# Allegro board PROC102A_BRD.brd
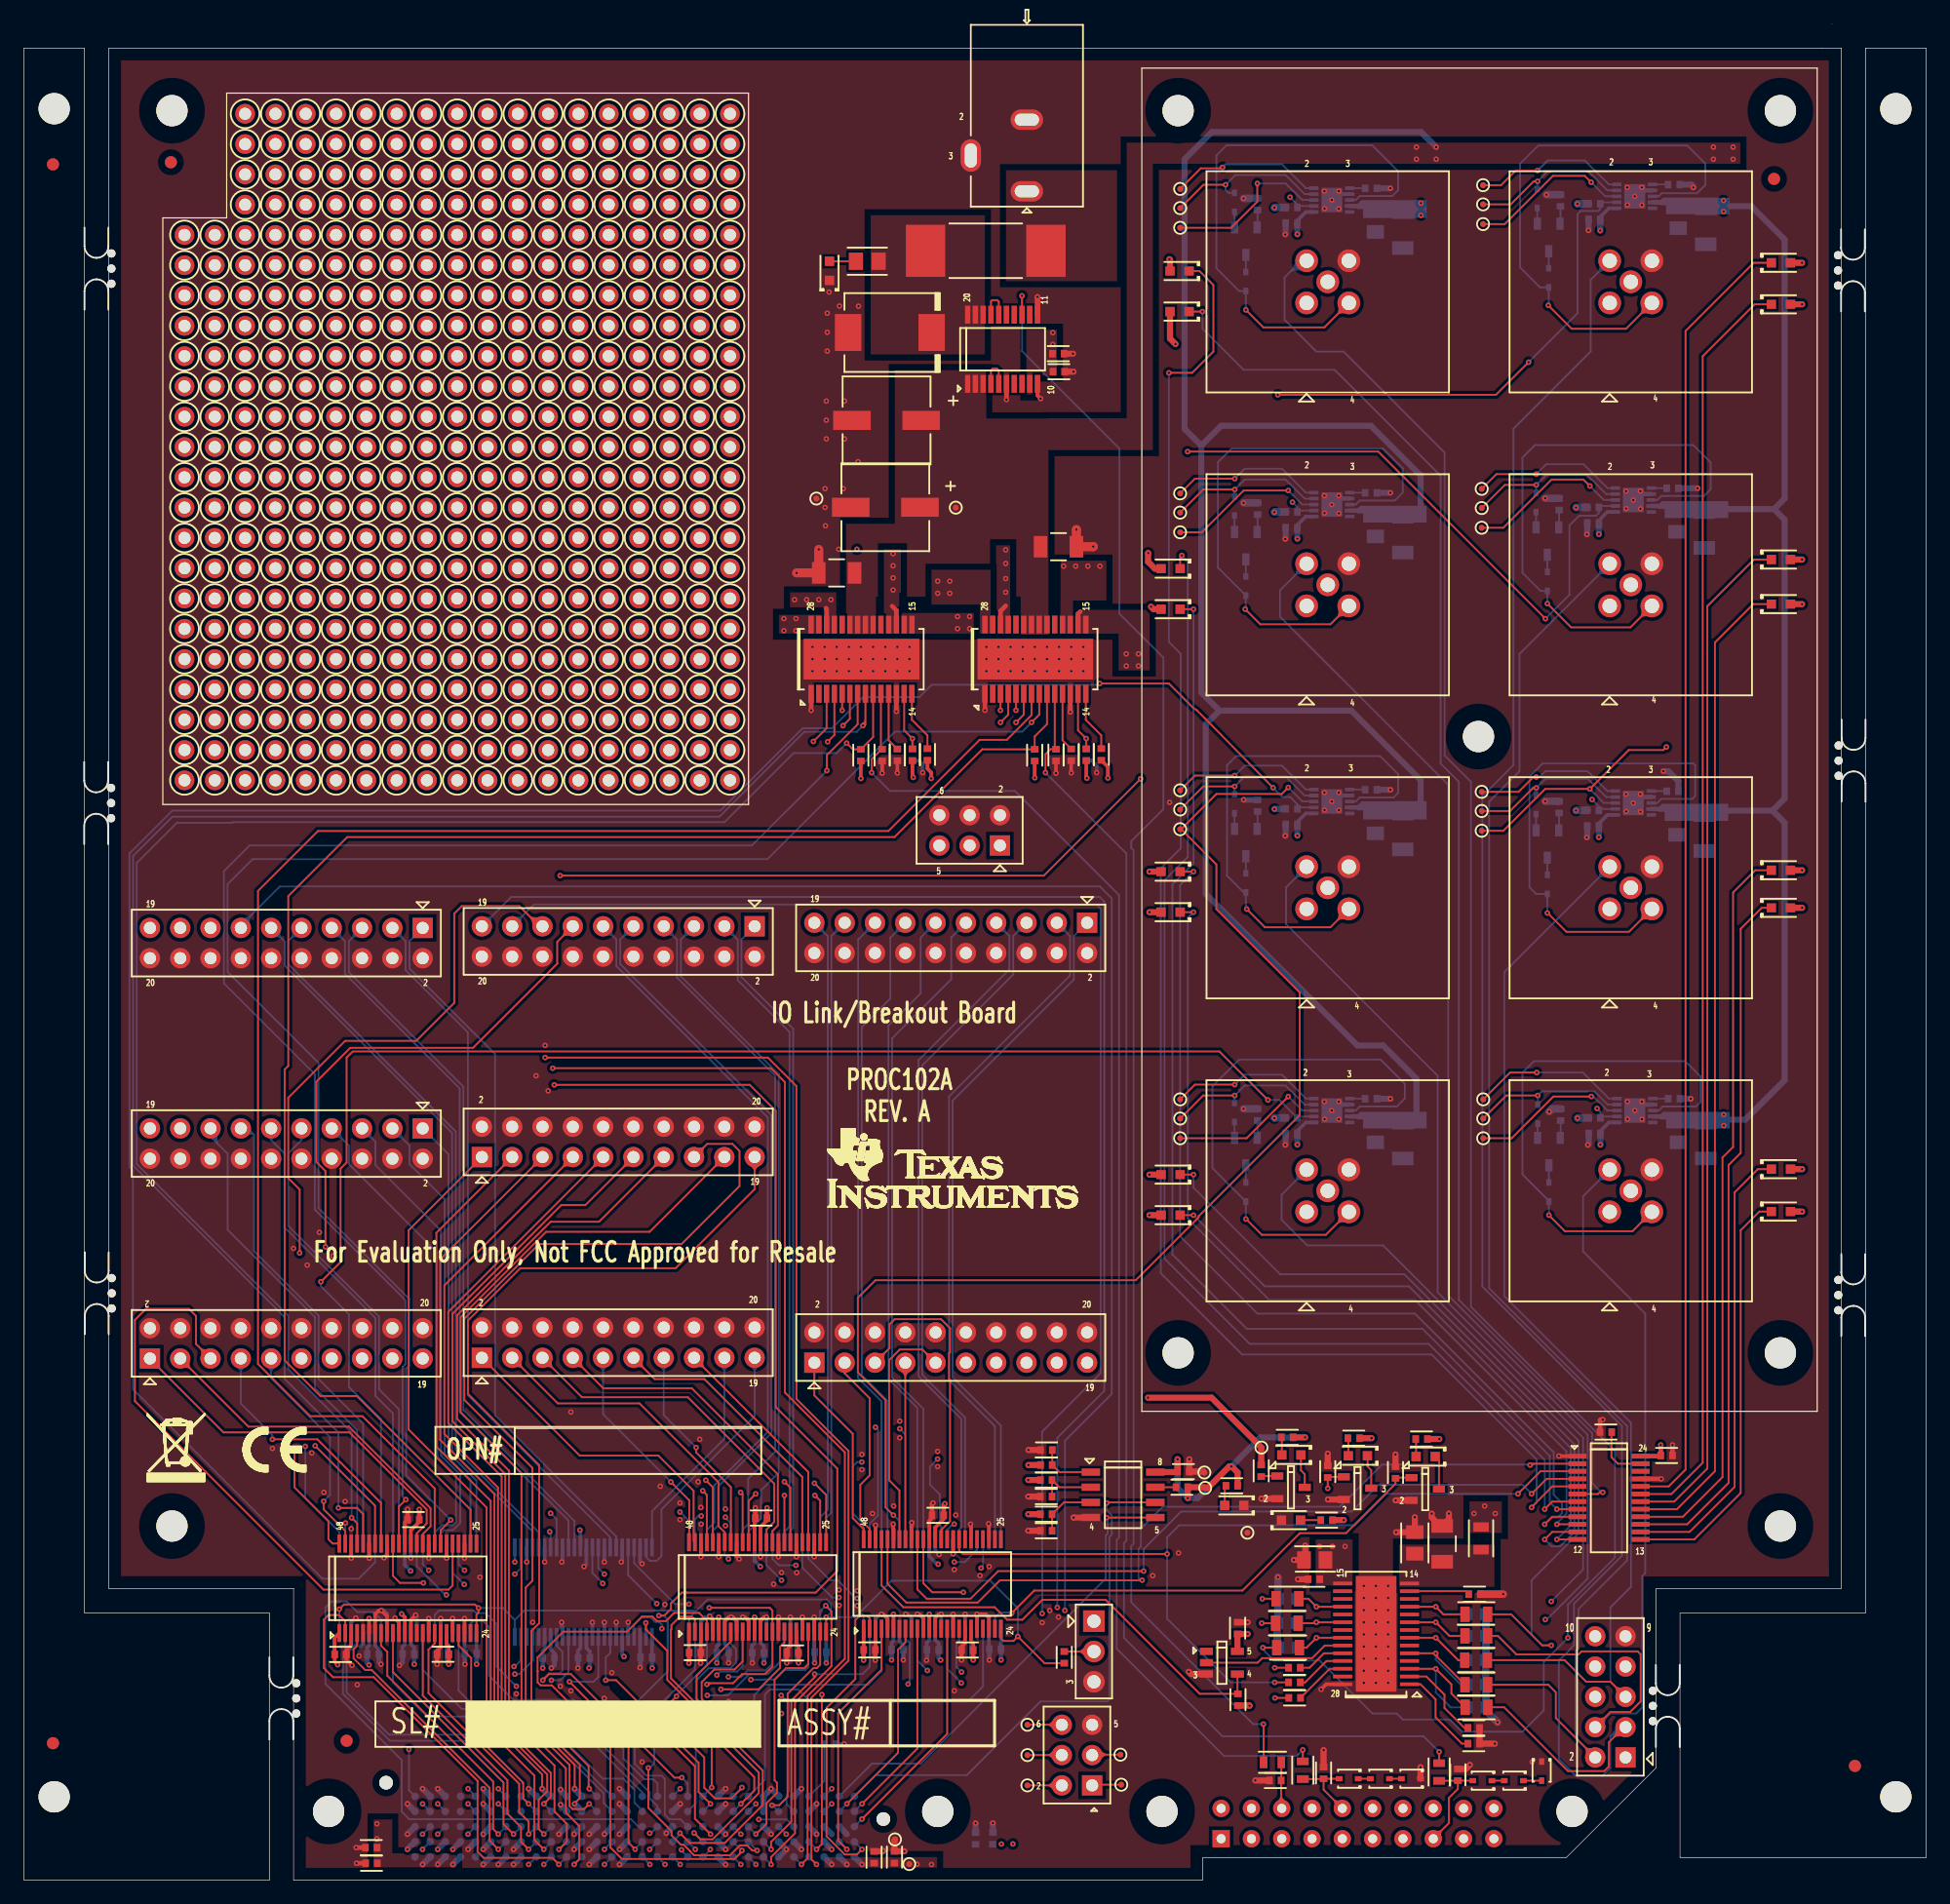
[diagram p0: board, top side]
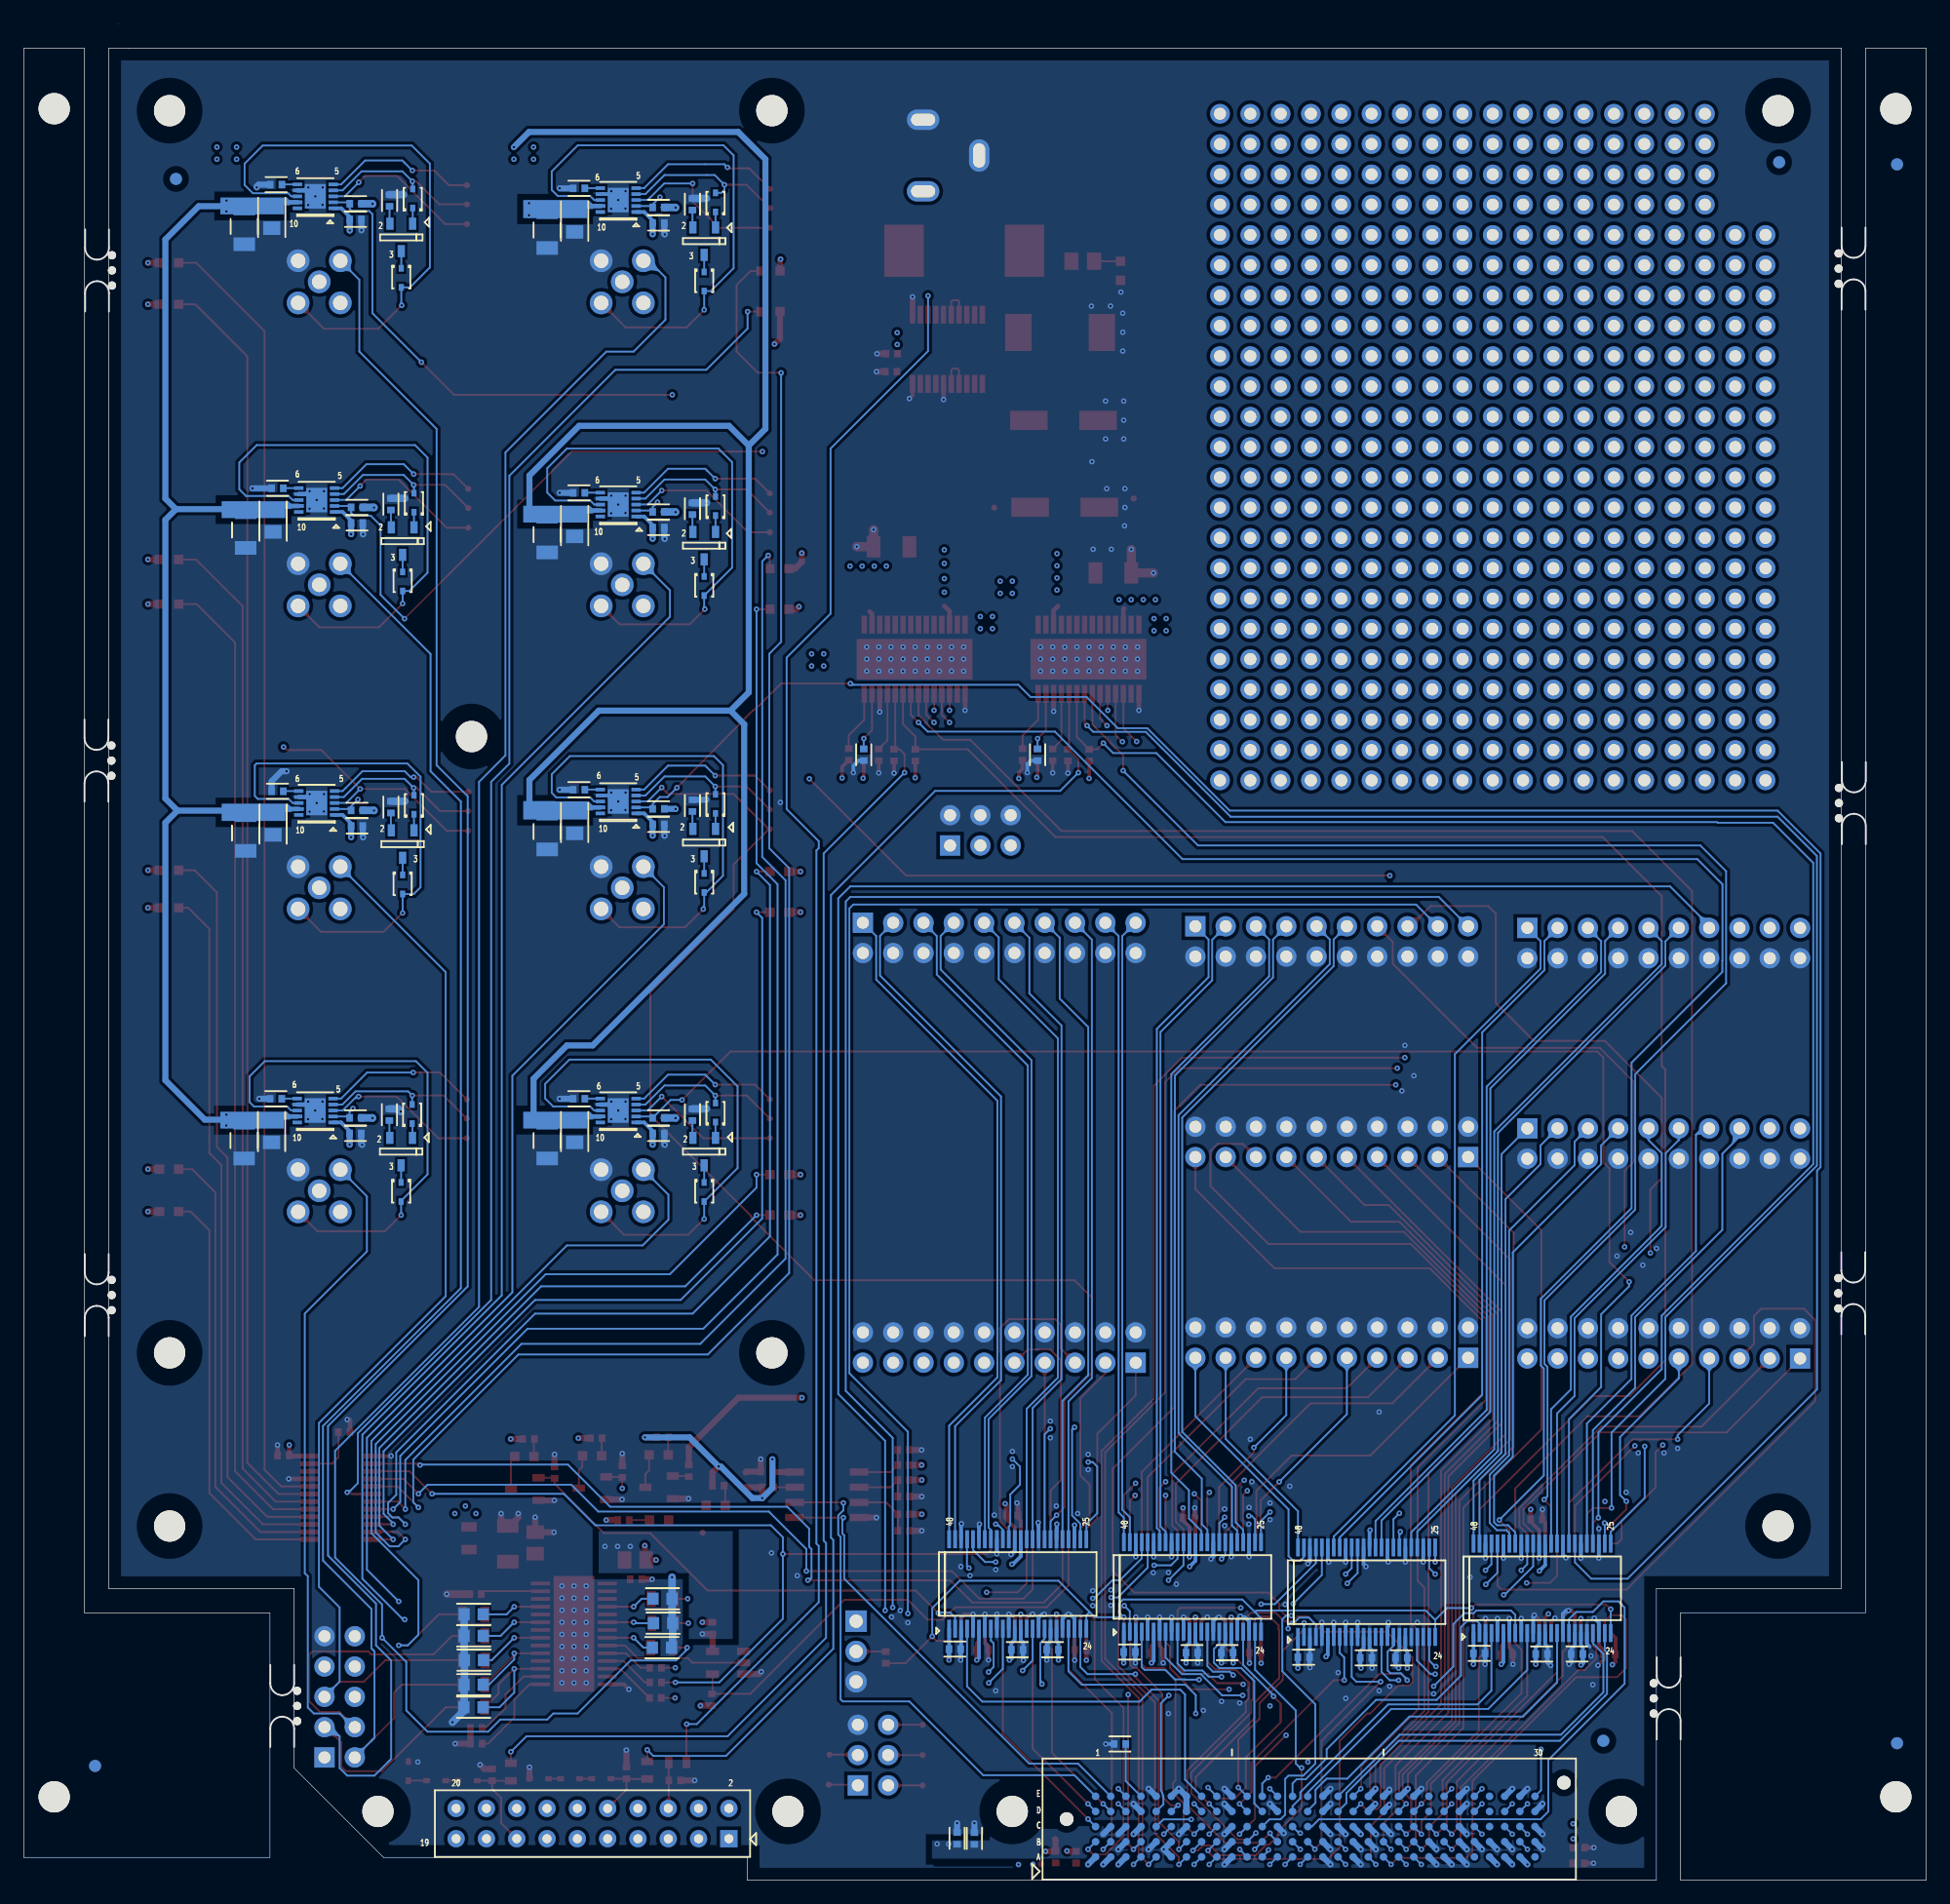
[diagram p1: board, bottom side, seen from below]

Outline 159.44 x 155.62 mm; copper layers: TOP, L02_GND1, L03_SIG1, L04_PWR, L05_GND2, BOTTOM. Coordinates in mm from the lower left corner of the outline.
Outline path: 0,153.59 5.08,153.59 5.08,22.42 20.58,22.42 20.58,0 0,0 0,153.59 ; 7.11,153.59 150.7,153.59 150.7,153.59 152.31,153.59 152.32,153.58 152.32,24.44 136.78,24.44 136.78,9.4 129.29,1.91 98.81,1.91 98.81,0 22.61,0 22.61,24.45 7.11,24.45 7.11,153.59 ; 138.81,22.41 154.35,22.41 154.35,153.59 159.44,153.59 159.44,1.91 138.81,1.91 138.81,22.41

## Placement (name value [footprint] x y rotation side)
C1  0.1uF  [CAP0402_0-75]  97.18 34.25 180 top
C2  1uF  [CAP0402_0-75]  81.22 3.51 90 bottom
C3  0.1uF  [CAP0402_0-75]  79.77 3.49 90 bottom
C4  1uF  [CAP0402_0-75]  29.14 1.42 180 top
C5  0.1uF  [CAP0402_0-75]  29.11 2.73 180 top
C6  1uF  [CAP0402_0-75]  72.97 1.93 90 top
C7  0.1uF  [CAP0402_0-75]  71.26 1.92 90 top
C8  0.1uF  [CAP0402_0-75]  81.41 19.37 180 bottom
C9  0.1uF  [CAP0402_0-75]  76.18 19.32 180 bottom
C10  0.1uF  [CAP0402_0-75]  73.22 19.32 0 bottom
C15  0.1uF  [CAP0402_0-75]  58.57 19.07 0 bottom
C16  0.1uF  [CAP0402_0-75]  66.76 19.12 180 bottom
C17  0.1uF  [CAP0402_0-75]  61.54 19.07 180 bottom
C20  0.1uF  [CAP0402_0-75]  61.79 30.36 180 top
C21  0.1uF  [CAP0402_0-75]  56.25 19.07 0 top
C22  0.1uF  [CAP0402_0-75]  64.43 19.05 180 top
C25  0.1uF  [CAP0402_0-75]  52.17 18.69 180 bottom
C26  0.1uF  [CAP0402_0-75]  43.98 18.64 0 bottom
C27  0.1uF  [CAP0402_0-75]  46.94 18.64 180 bottom
C30  0.1uF  [CAP0402_0-75]  32.23 18.96 180 bottom
C31  0.1uF  [CAP0402_0-75]  29.27 18.96 0 bottom
C32  0.1uF  [CAP0402_0-75]  37.46 19.01 180 bottom
C33  0.1uF  [CAP0402_0-75]  26.54 18.92 0 top
C34  0.1uF  [CAP0402_0-75]  35.13 18.94 180 top
C35  0.1uF  [CAP0402_0-75]  32.65 30.22 180 top
C44  0.1uF  [CAP0402_0-75]  70.88 19.3 0 top
C45  0.1uF  [CAP0402_0-75]  79.08 19.3 180 top
C46  0.1uF  [CAP0402_0-75]  76.6 30.58 180 top
C63  0.1uF  [CAP0402_0-75]  137.68 35.6 0 top
C64  1uF  [CAP0402_0-75]  131.52 113.78 180 bottom
C65  1uF  [CAP0402_0-75]  131.63 139.24 180 bottom
C66  10uF  [CAP1206_2]  140.96 138.64 270 bottom
C67  1uF  [CAP0805_1-5]  138.66 139.39 270 bottom
C68  10uF  [CAP1206_2]  140.85 113.19 270 bottom
C69  1uF  [CAP0805_1-5]  138.55 113.93 270 bottom
C70  10uF  [CAP1206_2]  140.97 62 270 bottom
C71  1uF  [CAP0805_1-5]  138.67 62.75 270 bottom
C72  1uF  [CAP0402_0-75]  131.65 62.6 180 bottom
C73  1uF  [CAP0402_0-75]  131.52 88.38 180 bottom
C74  1uF  [CAP0805_1-5]  138.55 88.53 270 bottom
C75  10uF  [CAP1206_2]  140.85 87.79 270 bottom
C76  10uF  [CAP1206_2]  115.57 87.91 270 bottom
C77  1uF  [CAP0805_1-5]  113.27 88.66 270 bottom
C78  1uF  [CAP0402_0-75]  106.25 88.5 180 bottom
C79  10uF  [CAP1206_2]  115.57 62 270 bottom
C80  1uF  [CAP0805_1-5]  113.27 62.75 270 bottom
C81  1uF  [CAP0402_0-75]  106.25 62.6 180 bottom
C82  1uF  [CAP0402_0-75]  106.25 138.92 180 bottom
C83  10uF  [CAP1206_2]  115.57 138.33 270 bottom
C84  1uF  [CAP0805_1-5]  113.27 139.08 270 bottom
C85  1uF  [CAP0402_0-75]  106.25 113.4 180 bottom
C86  10uF  [CAP1206_2]  115.57 112.8 270 bottom
C87  1uF  [CAP0805_1-5]  113.27 113.55 270 bottom
C88  10uF  [CAP1206_2]  86.72 111.79 0 top
C89  10uF  [CAP1206_2]  68.12 109.59 180 top
C90  0.001uF  [CAP0805_1]  116.58 28.27 90 top
C91  10uF  [CAP1206_2]  118.87 28.2 90 top
C92  2.2uF  [CAP0805_1-5]  108.19 26.84 180 top
C93  0.01uF  [CAP0402_0-75]  108.13 25.23 180 top
C94  0.01uF  [CAP0402_0-75]  101.73 21.13 90 top
C95  0.022uF  [CAP0603_1]  121.75 14.49 0 bottom
C96  0.022uF  [CAP0603_1]  121.74 16.38 0 bottom
C97  0.022uF  [CAP0603_1]  121.71 18.44 0 bottom
C98  0.022uF  [CAP0603_1]  121.74 20.48 0 bottom
C99  0.022uF  [CAP0603_1]  121.74 22.29 0 bottom
C100  0.022uF  [CAP0603_1]  105.91 23.59 180 bottom
C101  0.022uF  [CAP0603_1]  105.86 21.54 180 bottom
C102  0.022uF  [CAP0603_1]  105.96 19.49 180 bottom
C103  1uF  [CAP0402_0-75]  104.89 8.36 180 top
C104  0.1uF  [CAP0402_0-75]  108.93 8.99 90 top
C105  0.1uF  [CAP0402_0-75]  120.18 8.83 90 top
C106  1uF  [CAP0402_0-75]  86.7 127.97 0 top
C107  0.1uF  [CAP0402_0-75]  86.75 126.46 0 top
C108  100uF_35V  [CAPAE_DCASE_6-1]  72.3 122.38 180 top
C109  100uF_35V  [CAPAE_DCASE_6-1]  72.2 115.1 180 top
D1  1N4148WT  [DIO_SOD523]  127.8 134.33 270 bottom
D2  1N4148WT  [DIO_SOD523]  127.69 108.87 270 bottom
D3  1N4148WT  [DIO_SOD523]  127.82 57.69 270 bottom
D4  1N4148WT  [DIO_SOD523]  127.69 83.47 270 bottom
D5  1N4148WT  [DIO_SOD523]  102.42 83.6 270 bottom
D6  1N4148WT  [DIO_SOD523]  102.42 57.69 270 bottom
D7  1N4148WT  [DIO_SOD523]  102.42 134.02 270 bottom
D8  1N4148WT  [DIO_SOD523]  102.42 108.49 270 bottom
D9  1N4148WT  [DIO_SOD523]  111.04 8.5 180 top
D10  1N4148WT  [DIO_SOD523]  122.24 8.34 180 top
D11  1N4148WT  [DIO_SOD523]  113.65 8.5 180 top
D12  1N4148WT  [DIO_SOD523]  124.88 8.34 180 top
D13  1N4148WT  [DIO_SOD523]  116.26 8.5 180 top
D14  1N4148WT  [DIO_SOD523]  127.21 9.14 270 top
D15  SMCJ28A  [DIO_SMC]  72.58 129.74 180 top
D16  1N4148WT  [DIO_SOD523]  126.84 140.98 90 bottom
D17  1N4148WT  [DIO_SOD523]  126.74 115.48 90 bottom
D18  1N4148WT  [DIO_SOD523]  126.74 90.16 90 bottom
D19  1N4148WT  [DIO_SOD523]  126.89 64.22 90 bottom
D20  1N4148WT  [DIO_SOD523]  101.47 64.35 90 bottom
D21  1N4148WT  [DIO_SOD523]  101.47 90.23 90 bottom
D22  1N4148WT  [DIO_SOD523]  101.47 115.2 90 bottom
D23  1N4148WT  [DIO_SOD523]  101.47 140.65 90 bottom
DN1  CON_T4141012051-000_CIRDIN5  [CON_CIRDIN5_T4141012051_S_S_T_23]  132.91 132.23 90 top
DN2  CON_T4141012051-000_CIRDIN5  [CON_CIRDIN5_T4141012051_S_S_T_23]  132.91 106.83 90 top
DN3  CON_T4141012051-000_CIRDIN5  [CON_CIRDIN5_T4141012051_S_S_T_23]  132.91 81.43 90 top
DN4  CON_T4141012051-000_CIRDIN5  [CON_CIRDIN5_T4141012051_S_S_T_23]  132.91 56.03 90 top
DN5  CON_T4141012051-000_CIRDIN5  [CON_CIRDIN5_T4141012051_S_S_T_23]  107.51 56.03 90 top
DN6  CON_T4141012051-000_CIRDIN5  [CON_CIRDIN5_T4141012051_S_S_T_23]  107.51 81.43 90 top
DN7  CON_T4141012051-000_CIRDIN5  [CON_CIRDIN5_T4141012051_S_S_T_23]  107.51 106.83 90 top
DN8  CON_T4141012051-000_CIRDIN5  [CON_CIRDIN5_T4141012051_S_S_T_23]  107.51 132.23 90 top
F1  10A  [FUSE_397_410X110_SMD_2-9]  80.62 136.6 180 top
J1  CON_XMC_5X30_M  [CON_XMC5X30_SEAM-30-03-5-05-2-A_P_S_S_7-5]  51.2 5.12 180 bottom
J2  HDR_2X10  [HDR_2X10_TSW_100_S_T]  89.11 80.26 0 top
J3  HDR_2X10  [HDR_2X10_TSW_100_S_T]  61.25 79.97 0 top
J4  HDR_2X10  [HDR_2X10_TSW_100_S_T]  38.39 43.79 180 top
J5  HDR_2X10  [HDR_2X10_TSW_100_S_T]  33.43 79.83 0 top
J6  HDR_2X10  [HDR_2X10_TSW_100_S_T]  33.43 63.02 0 top
J7  HDR_2X10  [HDR_2X10_TSW_100_S_T]  38.39 60.62 180 top
J8  HDR_2X10  [HDR_2X10_TSW_100_S_T]  10.57 43.73 180 top
J9  HDR_2X10  [HDR_2X10_TSW_100_S_T]  66.25 43.38 180 top
J11  HDR_1X3  [HDR_3X1_100_S_T]  89.68 21.71 90 top
J12  RECP_2X10  [RECPT_2X10_68683-310_S_T_7-1]  100.35 3.47 0 bottom
J13  CON_PWRJACK3_PJ-102AH  [CON_PWRJACK3_PJ-102AH_P_R_T_11]  84.07 141.58 180 top
J17  RECP_2X3  [RECPT_2X3_PPTC032LFBN_S_T_8-5]  81.81 86.74 180 top
J18  HDR_2X3  [HDR_2X3_TSW-103-07-D_S_T_8-4]  89.53 7.95 90 top
J21  HDR_2X5  [HDR_5X2_100_S_T_8-6]  134.24 10.29 270 top
LD1  150060VS75000  [LED_150060SS75000_70X40_SMD_0-8]  117.49 35.51 180 top
LD2  150060VS75000  [LED_150060SS75000_70X40_SMD_0-8]  111.81 35.58 180 top
LD3  150060VS75000  [LED_150060SS75000_70X40_SMD_0-8]  106.2 30.18 0 top
LD4  150060VS75000  [LED_150060SS75000_70X40_SMD_0-8]  101.45 31.42 180 top
LD5  150060VS75000  [LED_150060SS75000_70X40_SMD_0-8]  106.23 35.65 180 top
LD6  150060RS55040  [LED_150060RS55040_70X40_SMD_0-5]  96.86 134.9 180 top
LD7  150060VS75000  [LED_150060SS75000_70X40_SMD_0-8]  96.86 131.5 180 top
LD8  150060RS55040  [LED_150060RS55040_70X40_SMD_0-5]  96.11 109.95 180 top
LD9  150060VS75000  [LED_150060SS75000_70X40_SMD_0-8]  96.11 106.55 180 top
LD10  150060RS55040  [LED_150060RS55040_70X40_SMD_0-5]  96.11 84.55 180 top
LD11  150060VS75000  [LED_150060SS75000_70X40_SMD_0-8]  96.11 81.15 180 top
LD12  150060RS55040  [LED_150060RS55040_70X40_SMD_0-5]  96.11 59.15 180 top
LD13  150060VS75000  [LED_150060SS75000_70X40_SMD_0-8]  96.11 55.75 180 top
LD14  150060RS55040  [LED_150060RS55040_70X40_SMD_0-5]  147.26 56.05 0 top
LD15  150060VS75000  [LED_150060SS75000_70X40_SMD_0-8]  147.26 59.6 0 top
LD16  150060RS55040  [LED_150060RS55040_70X40_SMD_0-5]  147.26 81.51 0 top
LD17  150060VS75000  [LED_150060SS75000_70X40_SMD_0-8]  147.26 84.66 0 top
LD18  150060RS55040  [LED_150060RS55040_70X40_SMD_0-5]  147.26 106.98 0 top
LD19  150060VS75000  [LED_150060SS75000_70X40_SMD_0-8]  147.26 110.71 0 top
LD20  150060RS55040  [LED_150060RS55040_70X40_SMD_0-5]  147.26 132.11 0 top
LD21  150060VS75000  [LED_150060SS75000_70X40_SMD_0-8]  147.26 135.59 0 top
LD22  150060VS75000  [LED_150060SS75000_70X40_SMD_0-8]  67.52 134.92 90 top
NOREF  -  []  29.47 14.99 0 top
NOREF#2  -  [unnamed#2]  95.39 5.76 0 top
NOREF#3  -  [unnamed#3]  36.32 112.52 0 top
NOREF#4  -  []  12.41 29.69 90 top
NOREF#5  -  [unnamed#3]  26.16 112.52 0 top
NOREF#6  -  [unnamed#3]  46.48 104.9 0 top
NOREF#7  -  [unnamed#3]  59.18 125.22 0 top
NOREF#8  -  [unnamed#3]  28.7 120.14 0 top
NOREF#9  -  [unnamed#3]  49.02 117.6 0 top
NOREF#10  -  [unnamed#3]  41.4 143 0 top
NOREF#11  -  [unnamed#3]  51.56 112.52 0 top
NOREF#12  -  [unnamed#3]  56.64 117.6 0 top
NOREF#13  -  [unnamed#3]  59.18 115.06 0 top
NOREF#14  -  [unnamed#3]  18.54 127.76 0 top
NOREF#15  -  [unnamed#3]  38.86 127.76 0 top
NOREF#16  -  [unnamed#3]  51.56 125.22 0 top
NOREF#17  -  [unnamed#3]  38.86 122.68 0 top
NOREF#18  -  [unnamed#3]  41.4 102.36 0 top
NOREF#19  -  [unnamed#3]  56.64 109.98 0 top
NOREF#20  -  [unnamed#3]  16 97.28 0 top
NOREF#21  -  [unnamed#3]  31.24 125.22 0 top
NOREF#22  -  [unnamed#3]  23.62 92.2 0 top
NOREF#23  -  [unnamed#3]  46.48 143 0 top
NOREF#24  -  [unnamed#3]  26.16 140.46 0 top
NOREF#25  -  [unnamed#3]  16 120.14 0 top
NOREF#26  -  [unnamed#3]  26.16 120.14 0 top
NOREF#27  -  [unnamed#3]  31.24 109.98 0 top
NOREF#28  -  [unnamed#4]  6.11 49.2 270 top
NOREF#29  -  [unnamed#3]  13.46 117.6 0 top
NOREF#30  -  [unnamed#3]  21.08 143 0 top
NOREF#31  -  [unnamed#3]  33.78 135.38 0 top
NOREF#32  -  [unnamed#3]  46.48 109.98 0 top
NOREF#33  -  [unnamed#3]  38.86 132.84 0 top
NOREF#34  -  [unnamed#3]  49.02 140.46 0 top
NOREF#35  -  [unnamed#3]  33.78 143 0 top
NOREF#36  -  [unnamed#3]  31.24 94.74 0 top
NOREF#37  -  [unnamed#3]  59.18 137.92 0 top
NOREF#38  -  [unnamed#3]  18.54 125.22 0 top
NOREF#39  -  [unnamed#3]  46.48 94.74 0 top
NOREF#40  -  [unnamed#3]  41.4 140.46 0 top
NOREF#41  -  [unnamed#3]  56.64 140.46 0 top
NOREF#42  -  [unnamed#3]  41.4 94.74 0 top
NOREF#43  -  [unnamed#3]  59.18 140.46 0 top
NOREF#44  -  [unnamed#3]  33.78 92.2 0 top
NOREF#45  -  [unnamed#3]  49.02 135.38 0 top
NOREF#46  -  [unnamed#3]  26.16 117.6 0 top
NOREF#47  -  [unnamed#3]  41.4 148.08 0 top
NOREF#48  -  [unnamed#3]  21.08 102.36 0 top
NOREF#49  -  [unnamed#3]  36.32 135.38 0 top
NOREF#50  -  [unnamed#3]  26.16 145.54 0 top
NOREF#51  -  [unnamed#3]  31.24 97.28 0 top
NOREF#52  -  [unnamed#3]  31.24 107.44 0 top
NOREF#53  -  [unnamed#3]  59.18 104.9 0 top
NOREF#54  -  [unnamed#3]  28.7 92.2 0 top
NOREF#55  -  [unnamed#3]  21.08 107.44 0 top
NOREF#56  -  [unnamed#3]  54.1 112.52 0 top
NOREF#57  -  [unnamed#3]  16 117.6 0 top
NOREF#58  -  [unnamed#4]  137.78 14.61 90 top
NOREF#59  -  []  0 153.59 0 top
NOREF#60  -  [unnamed#3]  49.02 107.44 0 top
NOREF#61  -  [unnamed#3]  36.32 94.74 0 top
NOREF#62  -  [unnamed#3]  59.18 130.3 0 top
NOREF#63  -  [unnamed#3]  41.4 92.2 0 top
NOREF#64  -  [unnamed#3]  31.24 92.2 0 top
NOREF#65  -  [unnamed#3]  38.86 117.6 0 top
NOREF#66  -  [unnamed#3]  23.62 145.54 0 top
NOREF#67  -  [unnamed#3]  26.16 130.3 0 top
NOREF#68  -  [unnamed#3]  46.48 97.28 0 top
NOREF#69  -  [unnamed#3]  13.46 107.44 0 top
NOREF#70  -  [unnamed#2]  156.9 148.51 0 top
NOREF#71  -  [unnamed#3]  54.1 140.46 0 top
NOREF#72  -  [unnamed#3]  51.56 140.46 0 top
NOREF#73  -  [unnamed#3]  43.94 112.52 0 top
NOREF#74  -  [unnamed#3]  41.4 107.44 0 top
NOREF#75  -  [unnamed#3]  49.02 130.3 0 top
NOREF#76  -  [unnamed#3]  36.32 148.08 0 top
NOREF#77  -  [unnamed#3]  23.62 135.38 0 top
NOREF#78  -  [unnamed#3]  51.56 130.3 0 top
NOREF#79  -  [unnamed#3]  18.54 140.46 0 top
NOREF#80  -  [unnamed#3]  33.78 107.44 0 top
NOREF#81  -  []  0 0 90 top
NOREF#82  -  [unnamed#3]  31.24 137.92 0 top
NOREF#83  -  [unnamed#3]  33.78 137.92 0 top
NOREF#84  -  [unnamed#3]  18.54 135.38 0 top
NOREF#85  -  [unnamed#3]  43.94 143 0 top
NOREF#86  -  [unnamed#3]  38.86 97.28 0 top
NOREF#87  -  [unnamed#3]  26.16 143 0 top
NOREF#88  -  [unnamed#3]  33.78 140.46 0 top
NOREF#89  -  [unnamed#3]  21.08 145.54 0 top
NOREF#90  -  [unnamed#3]  46.48 140.46 0 top
NOREF#91  -  [unnamed#3]  36.32 92.2 0 top
NOREF#92  -  [unnamed#3]  13.46 125.22 0 top
NOREF#93  -  [unnamed#2]  25.54 5.76 0 top
NOREF#94  -  [unnamed#3]  56.64 130.3 0 top
NOREF#95  -  [unnamed#3]  31.24 135.38 0 top
NOREF#96  -  [unnamed#3]  36.32 107.44 0 top
NOREF#97  -  [unnamed#3]  36.32 125.22 0 top
NOREF#98  -  [unnamed#2]  147.22 44.2 0 top
NOREF#99  -  [unnamed#2]  2.44 11.48 0 top
NOREF#100  -  [unnamed#3]  28.7 115.06 0 top
NOREF#101  -  [unnamed#3]  23.62 130.3 0 top
NOREF#102  -  [unnamed#2]  12.41 29.69 0 top
NOREF#103  -  [unnamed#2]  2.44 143.84 0 top
NOREF#104  -  [unnamed#3]  33.78 109.98 0 top
NOREF#105  -  [unnamed#3]  43.94 132.84 0 top
NOREF#106  -  [unnamed#3]  38.86 140.46 0 top
NOREF#107  -  [unnamed#3]  56.64 104.9 0 top
NOREF#108  -  [unnamed#3]  38.86 99.82 0 top
NOREF#109  -  [unnamed#3]  54.1 132.84 0 top
NOREF#110  -  [unnamed#3]  28.7 102.36 0 top
NOREF#111  -  [unnamed#3]  33.78 122.68 0 top
NOREF#112  -  [unnamed#3]  59.18 120.14 0 top
NOREF#113  -  [unnamed#3]  46.48 107.44 0 top
NOREF#114  -  [unnamed#3]  16 135.38 0 top
NOREF#115  -  [unnamed#3]  38.86 120.14 0 top
NOREF#116  -  [unnamed#3]  31.24 120.14 0 top
NOREF#117  -  [unnamed#3]  54.1 94.74 0 top
NOREF#118  -  [unnamed#3]  41.4 135.38 0 top
NOREF#119  -  [unnamed#3]  59.18 99.82 0 top
NOREF#120  -  [unnamed#3]  28.7 132.84 0 top
NOREF#121  -  [unnamed#3]  13.46 97.28 0 top
NOREF#122  -  [unnamed#3]  49.02 102.36 0 top
NOREF#123  -  [unnamed#3]  54.1 117.6 0 top
NOREF#124  -  [unnamed#3]  33.78 104.9 0 top
NOREF#125  -  [unnamed#3]  26.16 135.38 0 top
NOREF#126  -  [unnamed#3]  26.16 107.44 0 top
NOREF#127  -  [unnamed#3]  28.7 135.38 0 top
NOREF#128  -  [unnamed#3]  38.86 130.3 0 top
NOREF#129  -  [unnamed#3]  26.16 132.84 0 top
NOREF#130  -  [unnamed#3]  36.32 99.82 0 top
NOREF#131  -  [unnamed#3]  41.4 130.3 0 top
NOREF#132  -  [unnamed#3]  41.4 109.98 0 top
NOREF#133  -  [unnamed#3]  51.56 132.84 0 top
NOREF#134  -  [unnamed#3]  56.64 145.54 0 top
NOREF#135  -  [unnamed#3]  41.4 137.92 0 top
NOREF#136  -  [unnamed#3]  51.56 135.38 0 top
NOREF#137  -  [unnamed#3]  31.24 132.84 0 top
NOREF#138  -  [unnamed#3]  43.94 127.76 0 top
NOREF#139  -  [unnamed#3]  23.62 104.9 0 top
NOREF#140  -  [unnamed#3]  43.94 148.08 0 top
NOREF#141  -  [unnamed#3]  46.48 120.14 0 top
NOREF#142  -  [unnamed#3]  46.48 130.3 0 top
NOREF#143  -  [unnamed#3]  33.78 102.36 0 top
NOREF#144  -  [unnamed#3]  16 125.22 0 top
NOREF#145  -  [unnamed#4]  153.3 134.95 90 top
NOREF#146  -  [unnamed#3]  18.54 92.2 0 top
NOREF#147  -  [unnamed#3]  31.24 143 0 top
NOREF#148  -  [unnamed#3]  41.4 117.6 0 top
NOREF#149  -  [unnamed#3]  49.02 143 0 top
NOREF#150  -  [unnamed#3]  41.4 99.82 0 top
NOREF#151  -  [unnamed#4]  6.08 135.1 270 top
NOREF#152  -  [unnamed#3]  16 132.84 0 top
NOREF#153  -  [unnamed#3]  51.56 97.28 0 top
NOREF#154  -  [unnamed#3]  36.32 120.14 0 top
NOREF#155  -  [unnamed#3]  43.94 115.06 0 top
NOREF#156  -  [unnamed#3]  59.18 97.28 0 top
NOREF#157  -  [unnamed#3]  41.4 104.9 0 top
NOREF#158  -  [unnamed#3]  59.18 127.76 0 top
NOREF#159  -  [unnamed#3]  26.16 122.68 0 top
NOREF#160  -  [unnamed#3]  13.46 137.92 0 top
NOREF#161  -  [unnamed#3]  49.02 92.2 0 top
NOREF#162  -  [unnamed#3]  43.94 97.28 0 top
NOREF#163  -  [unnamed#3]  51.56 107.44 0 top
NOREF#164  -  [unnamed#3]  16 112.52 0 top
NOREF#165  -  [unnamed#3]  46.48 112.52 0 top
NOREF#166  -  [unnamed#3]  13.46 127.76 0 top
NOREF#167  -  [unnamed#3]  36.32 130.3 0 top
NOREF#168  -  [unnamed#3]  18.54 130.3 0 top
NOREF#169  -  [unnamed#3]  54.1 135.38 0 top
NOREF#170  -  [unnamed#3]  54.1 115.06 0 top
NOREF#171  -  [unnamed#3]  41.4 145.54 0 top
NOREF#172  -  [unnamed#3]  21.08 109.98 0 top
NOREF#173  -  [unnamed#3]  49.02 97.28 0 top
NOREF#174  -  [unnamed#3]  18.54 137.92 0 top
NOREF#175  -  [unnamed#3]  31.24 115.06 0 top
NOREF#176  -  [unnamed#3]  13.46 132.84 0 top
NOREF#177  -  [unnamed#3]  43.94 135.38 0 top
NOREF#178  -  [unnamed#3]  23.62 125.22 0 top
NOREF#179  -  [unnamed#3]  46.48 145.54 0 top
NOREF#180  -  [unnamed#3]  56.64 137.92 0 top
NOREF#181  -  [unnamed#3]  31.24 104.9 0 top
NOREF#182  -  [unnamed#3]  23.62 143 0 top
NOREF#183  -  [unnamed#3]  21.08 132.84 0 top
NOREF#184  -  [unnamed#3]  36.32 97.28 0 top
NOREF#185  -  [unnamed#3]  49.02 120.14 0 top
NOREF#186  -  [unnamed#3]  38.86 107.44 0 top
NOREF#187  -  [unnamed#3]  23.62 115.06 0 top
NOREF#188  -  [unnamed#3]  56.64 107.44 0 top
NOREF#189  -  [unnamed#3]  26.16 92.2 0 top
NOREF#190  -  [unnamed#4]  21.58 15.24 270 top
NOREF#191  -  [unnamed#3]  43.94 92.2 0 top
NOREF#192  -  [unnamed#3]  26.16 94.74 0 top
NOREF#193  -  [unnamed#3]  28.7 107.44 0 top
NOREF#194  -  [unnamed#3]  33.78 99.82 0 top
NOREF#195  -  [unnamed#3]  38.86 115.06 0 top
NOREF#196  -  [unnamed#3]  23.62 102.36 0 top
NOREF#197  -  [unnamed#3]  59.18 143 0 top
NOREF#198  -  [unnamed#3]  31.24 112.52 0 top
NOREF#199  -  [unnamed#3]  33.78 145.54 0 top
NOREF#200  -  [unnamed#3]  18.54 132.84 0 top
NOREF#201  -  [unnamed#3]  38.86 92.2 0 top
NOREF#202  -  [unnamed#3]  49.02 148.08 0 top
NOREF#203  -  [unnamed#3]  43.94 130.3 0 top
NOREF#204  -  []  27.41 -97.56 0 top
NOREF#205  -  [unnamed#3]  49.02 132.84 0 top
NOREF#206  -  [unnamed#3]  21.08 148.08 0 top
NOREF#207  -  [unnamed#3]  23.62 148.08 0 top
NOREF#208  -  [unnamed#2]  2.54 6.99 0 top
NOREF#209  -  [unnamed#3]  56.64 125.22 0 top
NOREF#210  -  [unnamed#2]  121.92 95.87 0 top
NOREF#211  -  [unnamed#3]  46.48 122.68 0 top
NOREF#212  -  [unnamed#3]  41.4 122.68 0 top
NOREF#213  -  [unnamed#3]  28.7 125.22 0 top
NOREF#214  -  [unnamed#3]  54.1 143 0 top
NOREF#215  -  [unnamed#2]  153.47 9.58 0 top
NOREF#216  -  [unnamed#3]  33.78 115.06 0 top
NOREF#217  -  [unnamed#3]  18.54 109.98 0 top
NOREF#218  -  [unnamed#3]  56.64 120.14 0 top
NOREF#219  -  [unnamed#3]  46.48 137.92 0 top
NOREF#220  -  [unnamed#3]  31.24 117.6 0 top
NOREF#221  -  [unnamed#3]  18.54 102.36 0 top
NOREF#222  -  [unnamed#3]  33.78 130.3 0 top
NOREF#223  -  [unnamed#3]  28.7 94.74 0 top
NOREF#224  -  [unnamed#3]  46.48 115.06 0 top
NOREF#225  -  [unnamed#3]  38.86 137.92 0 top
NOREF#226  -  [unnamed#3]  43.94 102.36 0 top
NOREF#227  -  [unnamed#3]  31.24 99.82 0 top
NOREF#228  -  [unnamed#3]  13.46 112.52 0 top
NOREF#229  -  [unnamed#3]  51.56 127.76 0 top
NOREF#230  -  [unnamed#3]  36.32 143 0 top
NOREF#231  -  [unnamed#3]  18.54 120.14 0 top
NOREF#232  -  []  12.41 148.34 0 top
NOREF#233  -  [unnamed#3]  36.32 132.84 0 top
NOREF#234  -  [unnamed#3]  26.16 115.06 0 top
NOREF#235  -  [unnamed#3]  33.78 127.76 0 top
NOREF#236  -  [unnamed#3]  16 99.82 0 top
NOREF#237  -  [unnamed#3]  26.16 125.22 0 top
NOREF#238  -  [unnamed#3]  18.54 107.44 0 top
NOREF#239  -  [unnamed#3]  16 137.92 0 top
NOREF#240  -  [unnamed#3]  31.24 148.08 0 top
NOREF#241  -  [unnamed#3]  33.78 112.52 0 top
NOREF#242  -  [unnamed#3]  28.7 117.6 0 top
NOREF#243  -  [unnamed#3]  51.56 102.36 0 top
NOREF#244  -  [unnamed#3]  28.7 145.54 0 top
NOREF#245  -  [unnamed#3]  54.1 104.9 0 top
NOREF#246  -  [unnamed#3]  26.16 97.28 0 top
NOREF#247  -  [unnamed#3]  36.32 115.06 0 top
NOREF#248  -  [unnamed#3]  16 92.2 0 top
NOREF#249  -  [unnamed#3]  56.64 135.38 0 top
NOREF#250  -  [unnamed#3]  41.4 97.28 0 top
NOREF#251  -  [unnamed#3]  33.78 125.22 0 top
NOREF#252  -  [unnamed#3]  21.08 120.14 0 top
NOREF#253  -  [unnamed#4]  153.33 49.05 90 top
NOREF#254  -  [unnamed#3]  21.08 117.6 0 top
NOREF#255  -  [unnamed#3]  18.54 115.06 0 top
NOREF#256  -  [unnamed#3]  43.94 109.98 0 top
NOREF#257  -  [unnamed#3]  38.86 102.36 0 top
NOREF#258  -  [unnamed#3]  38.86 125.22 0 top
NOREF#259  -  [unnamed#3]  18.54 117.6 0 top
NOREF#260  -  [unnamed#3]  38.86 143 0 top
NOREF#261  -  [unnamed#3]  51.56 122.68 0 top
NOREF#262  -  [unnamed#3]  23.62 120.14 0 top
NOREF#263  -  [unnamed#3]  21.08 99.82 0 top
NOREF#264  -  [unnamed#3]  28.7 140.46 0 top
NOREF#265  -  [unnamed#3]  51.56 115.06 0 top
NOREF#266  -  [unnamed#3]  18.54 148.08 0 top
NOREF#267  -  [unnamed#3]  49.02 109.98 0 top
NOREF#268  -  [unnamed#3]  13.46 115.06 0 top
NOREF#269  -  [unnamed#3]  31.24 140.46 0 top
NOREF#270  -  [unnamed#3]  18.54 143 0 top
NOREF#271  -  [unnamed#3]  16 102.36 0 top
NOREF#272  -  [unnamed#3]  13.46 92.2 0 top
NOREF#273  -  [unnamed#3]  49.02 99.82 0 top
NOREF#274  -  [unnamed#3]  28.7 112.52 0 top
NOREF#275  -  [unnamed#3]  16 127.76 0 top
NOREF#276  -  [unnamed#3]  59.18 145.54 0 top
NOREF#277  -  [unnamed#3]  56.64 92.2 0 top
NOREF#278  -  [unnamed#3]  31.24 127.76 0 top
NOREF#279  -  []  95.39 5.76 0 top
NOREF#280  -  [unnamed#3]  16 130.3 0 top
NOREF#281  -  [unnamed#3]  56.64 122.68 0 top
NOREF#282  -  [unnamed#4]  6.06 90.3 270 top
NOREF#283  -  [unnamed#3]  23.62 140.46 0 top
NOREF#284  -  [unnamed#3]  51.56 120.14 0 top
NOREF#285  -  [unnamed#3]  43.94 122.68 0 top
NOREF#286  -  [unnamed#3]  21.08 115.06 0 top
NOREF#287  -  [unnamed#3]  59.18 135.38 0 top
NOREF#288  -  [unnamed#3]  54.1 130.3 0 top
NOREF#289  -  [unnamed#3]  18.54 145.54 0 top
NOREF#290  -  [unnamed#2]  12.41 148.34 0 top
NOREF#291  -  [unnamed#3]  36.32 145.54 0 top
NOREF#292  -  [unnamed#3]  16 122.68 0 top
NOREF#293  -  []  -404.06 -63.87 0 top
NOREF#294  -  [unnamed#3]  36.32 104.9 0 top
NOREF#295  -  [unnamed#3]  18.54 94.74 0 top
NOREF#296  -  [unnamed#3]  13.46 135.38 0 top
NOREF#297  -  [unnamed#3]  41.4 125.22 0 top
NOREF#298  -  [unnamed#3]  33.78 148.08 0 top
NOREF#299  -  [unnamed#3]  49.02 112.52 0 top
NOREF#300  -  [unnamed#3]  23.62 117.6 0 top
NOREF#301  -  [unnamed#3]  51.56 109.98 0 top
NOREF#302  -  [unnamed#3]  26.16 109.98 0 top
NOREF#303  -  [unnamed#3]  38.86 148.08 0 top
NOREF#304  -  [unnamed#3]  13.46 94.74 0 top
NOREF#305  -  [unnamed#3]  49.02 145.54 0 top
NOREF#306  -  [unnamed#3]  18.54 99.82 0 top
NOREF#307  -  [unnamed#3]  23.62 94.74 0 top
NOREF#308  -  [unnamed#3]  46.48 132.84 0 top
NOREF#309  -  [unnamed#3]  21.08 97.28 0 top
NOREF#310  -  [unnamed#3]  21.08 112.52 0 top
NOREF#311  -  [unnamed#3]  49.02 127.76 0 top
NOREF#312  -  [unnamed#2]  76.6 5.76 0 top
NOREF#313  -  [unnamed#3]  46.48 148.08 0 top
NOREF#314  -  [unnamed#2]  146.69 142.62 0 top
NOREF#315  -  [unnamed#3]  51.56 117.6 0 top
NOREF#316  -  [unnamed#3]  28.7 137.92 0 top
NOREF#317  -  [unnamed#3]  31.24 130.3 0 top
NOREF#318  -  [unnamed#3]  43.94 120.14 0 top
NOREF#319  -  [unnamed#3]  26.16 127.76 0 top
NOREF#320  -  [unnamed#3]  59.18 109.98 0 top
NOREF#321  -  [unnamed#3]  49.02 137.92 0 top
NOREF#322  -  [unnamed#3]  23.62 99.82 0 top
NOREF#323  -  [unnamed#3]  26.16 148.08 0 top
NOREF#324  -  [unnamed#3]  18.54 112.52 0 top
NOREF#325  -  [unnamed#3]  16 109.98 0 top
NOREF#326  -  [unnamed#3]  56.64 127.76 0 top
NOREF#327  -  [unnamed#3]  28.7 143 0 top
NOREF#328  -  []  -52.42 47.01 0 top
NOREF#329  -  [unnamed#3]  56.64 132.84 0 top
NOREF#330  -  []  25.54 5.76 0 top
NOREF#331  -  [unnamed#3]  23.62 97.28 0 top
NOREF#332  -  [unnamed#3]  21.08 92.2 0 top
NOREF#333  -  [unnamed#3]  36.32 127.76 0 top
NOREF#334  -  [unnamed#3]  59.18 122.68 0 top
NOREF#335  -  [unnamed#3]  21.08 135.38 0 top
NOREF#336  -  [unnamed#3]  33.78 132.84 0 top
NOREF#337  -  [unnamed#3]  59.18 92.2 0 top
NOREF#338  -  [unnamed#3]  54.1 127.76 0 top
NOREF#339  -  [unnamed#3]  23.62 127.76 0 top
NOREF#340  -  [unnamed#3]  26.16 99.82 0 top
NOREF#341  -  [unnamed#3]  13.46 109.98 0 top
NOREF#342  -  [unnamed#3]  56.64 112.52 0 top
NOREF#343  -  [unnamed#2]  129.76 5.76 0 top
NOREF#344  -  [unnamed#2]  96.74 44.2 0 top
NOREF#345  -  [unnamed#3]  46.48 102.36 0 top
NOREF#346  -  [unnamed#3]  21.08 104.9 0 top
NOREF#347  -  [unnamed#2]  2.54 148.51 0 top
NOREF#348  -  [unnamed#3]  59.18 102.36 0 top
NOREF#349  -  [unnamed#3]  21.08 137.92 0 top
NOREF#350  -  [unnamed#3]  13.46 122.68 0 top
NOREF#351  -  [unnamed#3]  28.7 130.3 0 top
NOREF#352  -  [unnamed#3]  46.48 127.76 0 top
NOREF#353  -  [unnamed#3]  51.56 148.08 0 top
NOREF#354  -  [unnamed#3]  13.46 130.3 0 top
NOREF#355  -  [unnamed#3]  51.56 92.2 0 top
NOREF#356  -  [unnamed#3]  31.24 145.54 0 top
NOREF#357  -  [unnamed#3]  43.94 94.74 0 top
NOREF#358  -  [unnamed#3]  56.64 102.36 0 top
NOREF#359  -  [unnamed#3]  31.24 122.68 0 top
NOREF#360  -  [unnamed#3]  28.7 97.28 0 top
NOREF#361  -  [unnamed#3]  28.7 127.76 0 top
NOREF#362  -  [unnamed#3]  59.18 107.44 0 top
NOREF#363  -  [unnamed#3]  46.48 125.22 0 top
NOREF#364  -  [unnamed#3]  21.08 122.68 0 top
NOREF#365  -  [unnamed#3]  51.56 104.9 0 top
NOREF#366  -  [unnamed#3]  54.1 125.22 0 top
NOREF#367  -  [unnamed#3]  18.54 122.68 0 top
NOREF#368  -  [unnamed#3]  54.1 148.08 0 top
NOREF#369  -  [unnamed#3]  43.94 117.6 0 top
NOREF#370  -  [unnamed#2]  12.32 144.02 0 top
NOREF#371  -  [unnamed#3]  43.94 104.9 0 top
NOREF#372  -  [unnamed#3]  54.1 122.68 0 top
NOREF#373  -  [unnamed#2]  156.9 6.99 0 top
NOREF#374  -  [unnamed#3]  49.02 122.68 0 top
NOREF#375  -  [unnamed#3]  28.7 99.82 0 top
NOREF#376  -  [unnamed#3]  21.08 140.46 0 top
NOREF#377  -  [unnamed#3]  38.86 112.52 0 top
NOREF#378  -  [unnamed#3]  33.78 120.14 0 top
NOREF#379  -  [unnamed#3]  16 107.44 0 top
NOREF#380  -  [unnamed#3]  54.1 109.98 0 top
NOREF#381  -  [unnamed#3]  38.86 135.38 0 top
NOREF#382  -  [unnamed#3]  46.48 117.6 0 top
NOREF#383  -  [unnamed#3]  36.32 109.98 0 top
NOREF#384  -  [unnamed#3]  41.4 120.14 0 top
NOREF#385  -  [unnamed#3]  43.94 107.44 0 top
NOREF#386  -  [unnamed#3]  46.48 92.2 0 top
NOREF#387  -  [unnamed#3]  23.62 132.84 0 top
NOREF#388  -  [unnamed#3]  43.94 140.46 0 top
NOREF#389  -  [unnamed#3]  28.7 148.08 0 top
NOREF#390  -  [unnamed#3]  21.08 94.74 0 top
NOREF#391  -  []  -398.12 238.3 0 top
NOREF#392  -  [unnamed#3]  21.08 130.3 0 top
NOREF#393  -  [unnamed#3]  59.18 117.6 0 top
NOREF#394  -  [unnamed#3]  54.1 145.54 0 top
NOREF#395  -  [unnamed#3]  54.1 107.44 0 top
NOREF#396  -  [unnamed#3]  21.08 125.22 0 top
NOREF#397  -  [unnamed#3]  38.86 104.9 0 top
NOREF#398  -  [unnamed#3]  43.94 145.54 0 top
NOREF#399  -  [unnamed#3]  56.64 148.08 0 top
NOREF#400  -  [unnamed#3]  49.02 115.06 0 top
NOREF#401  -  [unnamed#3]  16 104.9 0 top
NOREF#402  -  [unnamed#3]  28.7 109.98 0 top
NOREF#403  -  [unnamed#3]  43.94 137.92 0 top
NOREF#404  -  [unnamed#3]  54.1 137.92 0 top
NOREF#405  -  [unnamed#3]  36.32 137.92 0 top
NOREF#406  -  [unnamed#3]  56.64 99.82 0 top
NOREF#407  -  [unnamed#3]  26.16 104.9 0 top
NOREF#408  -  [unnamed#3]  23.62 107.44 0 top
NOREF#409  -  [unnamed#2]  96.74 148.34 0 top
NOREF#410  -  [unnamed#3]  54.1 99.82 0 top
NOREF#411  -  [unnamed#3]  13.46 102.36 0 top
NOREF#412  -  [unnamed#3]  59.18 148.08 0 top
NOREF#413  -  [unnamed#3]  28.7 122.68 0 top
NOREF#414  -  [unnamed#3]  16 115.06 0 top
NOREF#415  -  [unnamed#3]  26.16 102.36 0 top
NOREF#416  -  [unnamed#3]  43.94 99.82 0 top
NOREF#417  -  [unnamed#3]  23.62 112.52 0 top
NOREF#418  -  [unnamed#3]  26.16 137.92 0 top
NOREF#419  -  [unnamed#3]  33.78 94.74 0 top
NOREF#420  -  [unnamed#3]  33.78 117.6 0 top
NOREF#421  -  [unnamed#3]  49.02 125.22 0 top
NOREF#422  -  [unnamed#3]  38.86 109.98 0 top
NOREF#423  -  [unnamed#3]  54.1 102.36 0 top
NOREF#424  -  [unnamed#3]  56.64 115.06 0 top
NOREF#425  -  [unnamed#3]  23.62 109.98 0 top
NOREF#426  -  [unnamed#3]  54.1 97.28 0 top
NOREF#427  -  [unnamed#3]  49.02 104.9 0 top
NOREF#428  -  [unnamed#3]  56.64 143 0 top
NOREF#429  -  [unnamed#3]  33.78 97.28 0 top
NOREF#430  -  [unnamed#3]  51.56 137.92 0 top
NOREF#431  -  [unnamed#3]  36.32 122.68 0 top
NOREF#432  -  [unnamed#3]  28.7 104.9 0 top
NOREF#433  -  [unnamed#3]  23.62 122.68 0 top
NOREF#434  -  [unnamed#3]  49.02 94.74 0 top
NOREF#435  -  [unnamed#3]  51.56 99.82 0 top
NOREF#436  -  [unnamed#3]  54.1 92.2 0 top
NOREF#437  -  [unnamed#3]  41.4 127.76 0 top
NOREF#438  -  [unnamed#3]  18.54 104.9 0 top
NOREF#439  -  [unnamed#3]  13.46 99.82 0 top
NOREF#440  -  [unnamed#3]  41.4 115.06 0 top
NOREF#441  -  [unnamed#3]  51.56 143 0 top
NOREF#442  -  [unnamed#3]  36.32 140.46 0 top
NOREF#443  -  [unnamed#3]  38.86 94.74 0 top
NOREF#444  -  [unnamed#3]  23.62 137.92 0 top
NOREF#445  -  [unnamed#3]  51.56 94.74 0 top
NOREF#446  -  [unnamed#3]  13.46 104.9 0 top
NOREF#447  -  [unnamed#3]  41.4 132.84 0 top
NOREF#448  -  [unnamed#3]  51.56 145.54 0 top
NOREF#449  -  [unnamed#3]  16 94.74 0 top
NOREF#450  -  []  -387.25 -135.94 0 top
NOREF#451  -  [unnamed#3]  56.64 97.28 0 top
NOREF#452  -  [unnamed#3]  13.46 120.14 0 top
NOREF#453  -  [unnamed#3]  18.54 97.28 0 top
NOREF#454  -  [unnamed#3]  59.18 132.84 0 top
NOREF#455  -  [unnamed#3]  43.94 125.22 0 top
NOREF#456  -  [unnamed#3]  59.18 112.52 0 top
NOREF#457  -  [unnamed#3]  36.32 117.6 0 top
NOREF#458  -  [unnamed#3]  21.08 127.76 0 top
NOREF#459  -  [unnamed#3]  38.86 145.54 0 top
NOREF#460  -  [unnamed#4]  153.35 93.85 90 top
NOREF#461  -  [unnamed#3]  46.48 99.82 0 top
NOREF#462  -  [unnamed#3]  41.4 112.52 0 top
NOREF#463  -  [unnamed#3]  31.24 102.36 0 top
NOREF#464  -  [unnamed#3]  36.32 102.36 0 top
NOREF#465  -  [unnamed#2]  147.22 29.69 0 top
NOREF#466  -  [unnamed#3]  59.18 94.74 0 top
NOREF#467  -  [unnamed#3]  56.64 94.74 0 top
NOREF#468  -  [unnamed#2]  147.22 148.34 0 top
NOREF#469  -  [unnamed#2]  27.05 11.68 0 top
NOREF#470  -  [unnamed#3]  46.48 135.38 0 top
NOREF#471  -  [unnamed#3]  54.1 120.14 0 top
NOREF#472  -  [unnamed#2]  153.47 9.58 180 bottom
NOREF#473  -  [unnamed#2]  146.69 142.62 180 bottom
NOREF#474  -  [unnamed#2]  27.05 11.68 180 bottom
NOREF#475  -  [unnamed#2]  2.44 143.84 180 bottom
NOREF#476  -  [unnamed#2]  2.44 11.48 180 bottom
NOREF#477  -  [unnamed#2]  12.32 144.02 180 bottom
Q1  BSS138LT1G  [SOT23-123_1-2]  117.45 32.79 0 top
Q2  BSS138LT1G  [SOT23-123_1-2]  111.77 32.86 0 top
Q3  BSS138LT1G  [SOT23-123_1-2]  106.2 32.93 0 top
Q4  PBSS4160T  [SOT23-123_1-1]  127.8 137.71 270 bottom
Q5  PBSS4160T  [SOT23-123_1-1]  127.69 112.26 270 bottom
Q6  PBSS4160T  [SOT23-123_1-1]  127.82 61.08 270 bottom
Q7  PBSS4160T  [SOT23-123_1-1]  127.69 86.86 270 bottom
Q8  PBSS4160T  [SOT23-123_1-1]  102.42 61.08 270 bottom
Q9  PBSS4160T  [SOT23-123_1-1]  102.42 86.98 270 bottom
Q10  PBSS4160T  [SOT23-123_1-1]  102.42 137.4 270 bottom
Q11  PBSS4160T  [SOT23-123_1-1]  102.42 111.88 270 bottom
R1  0E  [RES0402_0-5]  67.57 11.42 180 bottom
R2  10K  [RES0402_0-5]  85.7 34.8 0 top
R3  10K  [RES0402_0-5]  85.69 33.54 0 top
R4  10K  [RES0402_0-5]  85.69 30.68 0 top
R5  10K  [RES0402_0-5]  97.06 32.94 180 top
R6  10K  [RES0402_0-5]  85.71 36.06 180 top
R7  10K  [RES0402_0-5]  85.69 32.16 180 top
R8  10K  [RES0402_0-5]  85.69 29.29 180 top
R64  220E  [RES0402_0-5]  117.14 36.98 180 top
R65  220E  [RES0402_0-5]  111.46 37.05 180 top
R66  220E  [RES0402_0-5]  109.19 30.18 180 top
R67  220E  [RES0402_0-5]  101.24 33.06 180 top
R68  220E  [RES0402_0-5]  105.89 37.12 180 top
R69  10K  [RES0402_0-5]  114.96 34.18 90 top
R70  10K  [RES0402_0-5]  109.28 34.25 90 top
R71  10K  [RES0402_0-5]  103.71 34.32 270 top
R72  10K  [RES0402_0-5]  87.2 18.68 90 top
R73  10K  [RES0402_0-5]  132.59 37.57 180 top
R74  0E  [RES0402_0-5]  138.3 142.14 0 bottom
R75  0E  [RES0402_0-5]  138.18 116.69 0 bottom
R76  10K  [RES0402_0-5]  131.63 140.54 180 bottom
R77  10K  [RES0402_0-5]  131.52 115.08 180 bottom
R78  240E_1%  [RES0402_0-5]  128.79 140.81 90 bottom
R79  240E_1%  [RES0402_0-5]  128.67 115.35 90 bottom
R80  0E  [RES0402_0-5]  138.31 65.51 0 bottom
R81  10K  [RES0402_0-5]  131.65 63.9 180 bottom
R82  0E  [RES0402_0-5]  138.18 91.29 0 bottom
R83  10K  [RES0402_0-5]  131.52 89.68 180 bottom
R84  240E_1%  [RES0402_0-5]  128.8 64.17 90 bottom
R85  240E_1%  [RES0402_0-5]  128.67 89.95 90 bottom
R86  0E  [RES0402_0-5]  112.91 65.51 0 bottom
R87  0E  [RES0402_0-5]  112.91 91.41 0 bottom
R88  10K  [RES0402_0-5]  106.25 89.81 180 bottom
R89  10K  [RES0402_0-5]  106.25 63.9 180 bottom
R90  240E_1%  [RES0402_0-5]  103.4 64.17 90 bottom
R91  240E_1%  [RES0402_0-5]  103.4 90.08 90 bottom
R92  0E  [RES0402_0-5]  112.91 141.83 0 bottom
R93  0E  [RES0402_0-5]  112.91 116.31 0 bottom
R94  10K  [RES0402_0-5]  106.25 140.23 180 bottom
R95  10K  [RES0402_0-5]  106.25 114.7 180 bottom
R96  240E_1%  [RES0402_0-5]  103.4 140.5 90 bottom
R97  240E_1%  [RES0402_0-5]  103.4 114.97 90 bottom
R98  0E  [RES0402_0-5]  89.04 94.35 270 top
R99  10K  [RES0402_0-5]  84.72 94.31 90 top
R100  0E  [RES0402_0-5]  90.3 94.37 270 top
R101  0E  [RES0402_0-5]  74.47 94.35 270 top
R102  10K  [RES0402_0-5]  70.15 94.31 90 top
R103  0E  [RES0402_0-5]  75.73 94.37 270 top
R104  3.32K_1%  [RES0402_0-5]  87.78 94.34 270 top
R105  768E_1%  [RES0402_0-5]  86.5 94.32 270 top
R106  0E  [RES0402_0-5]  89.04 94.35 90 bottom
R107  3.32K_1%  [RES0402_0-5]  73.21 94.34 270 top
R108  768E_1%  [RES0402_0-5]  71.93 94.32 270 top
R109  0E  [RES0402_0-5]  74.47 94.35 90 bottom
R111  1.2K_1%  [RES_MELF0102_1-1]  121.75 14.49 180 top
R112  1.2K_1%  [RES_MELF0102_1-1]  121.74 16.38 180 top
R113  1.2K_1%  [RES_MELF0102_1-1]  121.71 18.44 180 top
R114  1.2K_1%  [RES_MELF0102_1-1]  121.74 20.48 180 top
R115  1.2K_1%  [RES_MELF0102_1-1]  121.74 22.29 180 top
R116  1.2K_1%  [RES_MELF0102_1-1]  105.91 23.59 0 top
R117  1.2K_1%  [RES_MELF0102_1-1]  105.86 21.54 0 top
R118  1.2K_1%  [RES_MELF0102_1-1]  105.96 19.49 0 top
R119  0E  [RES0402_0-5]  106.49 16.58 180 top
R120  10K  [RES0402_0-5]  101.76 15.13 90 top
R121  0E  [RES0402_0-5]  106.51 15.28 0 top
R122  0E  [RES0402_0-5]  106.49 17.81 0 top
R123  0E  [RES0402_0-5]  121.52 11.44 180 top
R124  0E  [RES0402_0-5]  121.52 12.76 180 top
R125  25K_0.1%  [RES0402_1]  121.59 23.98 0 top
R126  10K  [RES0603_0-5]  104.65 9.88 180 top
R127  10K  [RES0603_0-5]  107.19 9.22 90 top
R128  10K  [RES0603_0-5]  118.62 9.07 270 top
R130  49.9E_1%  [RES_MELF0102_1-1]  122.13 28.66 90 top
R131  4.7K  [RES0805_0-75]  70.68 135.72 180 top
TP1  -  [TP20_SMD]  74.21 1.35 0 top
TP2  -  [TP20_SMD]  99.01 32.89 0 top
TP3  -  [TP20_SMD]  103.72 36.27 270 top
TP4  -  [TP20_SMD]  73.01 3.41 0 top
TP5  -  [TP20_SMD]  102.55 29.13 0 top
TP6  -  [TP20_SMD]  98.94 34.18 0 top
TP7  -  [TP20_SMD]  122.3 140.49 90 top
TP8  -  [TP20_SMD]  122.3 138.83 0 top
TP9  -  [TP20_SMD]  122.3 142.1 0 top
TP10  -  [TP20_SMD]  122.19 115.03 90 top
TP11  -  [TP20_SMD]  122.19 113.38 0 top
TP12  -  [TP20_SMD]  122.19 116.64 0 top
TP13  -  [TP20_SMD]  122.19 89.63 90 top
TP14  -  [TP20_SMD]  122.19 87.98 0 top
TP15  -  [TP20_SMD]  122.19 91.24 0 top
TP16  -  [TP20_SMD]  122.31 63.85 90 top
TP17  -  [TP20_SMD]  122.31 62.2 0 top
TP18  -  [TP20_SMD]  122.31 65.46 0 top
TP19  -  [TP20_SMD]  96.91 63.85 90 top
TP20  -  [TP20_SMD]  96.91 62.2 0 top
TP21  -  [TP20_SMD]  96.91 65.46 0 top
TP22  -  [TP20_SMD]  96.91 89.76 90 top
TP23  -  [TP20_SMD]  96.91 88.1 0 top
TP24  -  [TP20_SMD]  96.91 91.37 0 top
TP25  -  [TP20_SMD]  96.91 114.65 90 top
TP26  -  [TP20_SMD]  96.91 113 0 top
TP27  -  [TP20_SMD]  96.91 116.26 0 top
TP28  -  [TP20_SMD]  96.91 140.18 90 top
TP29  -  [TP20_SMD]  96.91 138.52 0 top
TP30  -  [TP20_SMD]  96.91 141.78 0 top
TP31  -  [TP20_SMD]  84.11 7.95 0 top
TP32  -  [TP20_SMD]  84.11 10.49 0 top
TP33  -  [TP20_SMD]  84.11 13.03 0 top
TP34  -  [TP20_SMD]  91.97 8 0 top
TP35  -  [TP20_SMD]  91.91 10.52 0 top
TP36  -  [TP20_SMD]  66.42 115.82 0 top
TP37  -  [TP20_SMD]  78.11 115.06 0 top
U1  CAT24C256WI-GT3  [SOIC8_1-8]  92.13 32.3 0 top
U2  TS3L301DGGR  [TSSOP48_19-68_500X245_1-2]  76.14 24.83 90 bottom
U4  TS3L301DGGR  [TSSOP48_19-68_500X245_1-2]  61.49 24.58 90 bottom
U7  TS3L301DGGR  [TSSOP48_19-68_500X245_1-2]  61.49 24.58 90 top
U9  TS3L301DGGR  [TSSOP48_19-68_500X245_1-2]  46.9 24.14 90 bottom
U11  TS3L301DGGR  [TSSOP48_19-68_500X245_1-2]  32.18 24.47 90 bottom
U12  TS3L301DGGR  [TSSOP48_19-68_500X245_1-2]  32.18 24.47 90 top
U17  TS3L301DGGR  [TSSOP48_19-68_500X245_1-2]  76.14 24.83 90 top
U26  TLC59282DBQR  [QSOP24_25_340X150_1-8]  132.86 32.05 0 top
U27  TIOL111DMWR  [VSON10_19-68_120X100_1]  135.01 141.16 0 bottom
U28  TIOL111DMWR  [VSON10_19-68_120X100_1]  134.89 115.7 0 bottom
U29  TIOL111DMWR  [VSON10_19-68_120X100_1]  135.02 64.52 0 bottom
U30  TIOL111DMWR  [VSON10_19-68_120X100_1]  134.89 90.3 0 bottom
U31  TIOL111DMWR  [VSON10_19-68_120X100_1]  109.62 64.52 0 bottom
U32  TIOL111DMWR  [VSON10_19-68_120X100_1]  109.62 90.43 0 bottom
U33  TIOL111DMWR  [VSON10_19-68_120X100_1]  109.62 115.32 0 bottom
U34  TIOL111DMWR  [VSON10_19-68_120X100_1]  109.62 140.85 0 bottom
U35  TPS4H160BQPWPRQ1  [HTSSOP28_LM5175-Q1_180X390_1-2]  84.78 102.36 90 top
U36  TPS4H160BQPWPRQ1  [HTSSOP28_LM5175-Q1_180X390_1-2]  70.21 102.36 90 top
U37  SN65HVS882PWPR  [ETSSOP28_SN65HVS885_390X180_1-2]  113.33 20.65 180 top
U38  SN74LVC1G07DBVR  [SOT23-5]  100.41 18.23 0 top
U39  INA253A2IPWR  [TSSOP20_25-59_260X180_1-2]  82.03 128.34 90 top

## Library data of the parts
C1-C10 C15-C17 C20-C22 C25-C27 C30-C35 C44-C46 C63-C107 = CAP
C108 C109 = CAP_POL
D1-D14 D16-D23 = DIODE
D15 = DIODE_TVS
DN1-DN8 = CON_T4143012051_CIRDIN5_S
F1 = FUSE
J1 = CON_XMC30X5_M_SEAM
J2-J9 = HEADER_10X2
J11 = HEADER_3X1
J12 = RECP_10X2
J13 = CON_PWRJACK3_PJ-102A
J17 = RECP_3X2
J18 = HEADER_3X2
J21 = HEADER_5X2
LD1-LD22 = DIODE_LED
Q1-Q3 = MOSFET_BSS138W
Q4-Q11 = NPN_123_SOT23-3
R1-R8 R64-R97 R99 R102 R104 R105 R107 R108 R111-R118 R120 R125-R128 R130 R131 = RESISTOR
R98 R100 R101 R103 R106 R109 R119 R121-R124 = RESISTOR: signal model: RESISTOR_RES0402_22E_1%_22E_1%
TP1-TP37 = TESTPOINT
U1 = CAT24C256WI-GT3_SOIC8
U2 U4 U7 U9 U11 U12 U17 = TS3L301_TSSOP48
U26 = TLC59282_SSOP24
U27-U34 = TIOL111_VSON10
U35 U36 = TPS4H160-Q1_HTSSOP28
U37 = SN65HVS882PWPR_HTSSOP28
U38 = SN74LVC1G07DBVR_SOT23-5
U39 = INA253A_TSSOP20

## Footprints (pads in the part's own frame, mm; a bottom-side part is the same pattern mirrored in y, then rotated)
CAP0402_0-75
  rect 0.559x0.635 smd: 1(-0.49,0) 2(0.49,0)
CAP0603_1
  rect 0.94x1.016 smd: 1(-0.8,0) 2(0.8,0)
CAP0805_1
  rect 1.143x1.448 smd: 1(-0.9,0) 2(0.9,0)
CAP0805_1-5
  rect 1.143x1.448 smd: 1(-0.9,0) 2(0.9,0)
CAP1206_2
  rect 1.143x1.803 smd: 1(-1.5,0) 2(1.5,0)
CAPAE_DCASE_6-1
  rect 3.15x1.6 smd: 1(-2.9,0) 2(2.9,0)
CON_CIRDIN5_T4141012051_S_S_T_23
  round 1.905 hole 1.219: 1(0,0) 2(3.536,0) 3(3.536,-3.536) 4(0,-3.536) 5(1.768,-1.768)
CON_PWRJACK3_PJ-102AH_P_R_T_11
  oval 2.718x1.702 hole 2.032x1.016: 1(0,0) 2(0,-6)
  oval 1.702x2.718 hole 1.016x2.032: 3(4.7,-3)
CON_XMC5X30_SEAM-30-03-5-05-2-A_P_S_S_7-5
  round 1.143 hole 1.27 unplated: (-20.84,0) (20.84,3.05)
  round 0.635 smd: A1(-18.415,-3.17) A2(-17.145,-3.17) A3(-15.875,-3.17) A4(-14.605,-3.17) A5(-13.335,-3.17) A6(-12.065,-3.17) A7(-10.795,-3.17) A8(-9.525,-3.17) A9(-8.255,-3.17) A10(-6.985,-3.17) A11(-5.715,-3.17) A12(-4.445,-3.17) A13(-3.175,-3.17) A14(-1.905,-3.17) A15(-0.635,-3.17) A16(0.635,-3.17) A17(1.905,-3.17) A18(3.175,-3.17) A19(4.445,-3.17) A20(5.715,-3.17) A21(6.985,-3.17) A22(8.255,-3.17) A23(9.525,-3.17) A24(10.795,-3.17) A25(12.065,-3.17) A26(13.335,-3.17) A27(14.605,-3.17) A28(15.875,-3.17) A29(17.145,-3.17) A30(18.415,-3.17) B1(-18.415,-1.9) B2(-17.145,-1.9) B3(-15.875,-1.9) B4(-14.605,-1.9) B5(-13.335,-1.9) B6(-12.065,-1.9) B7(-10.795,-1.9) B8(-9.525,-1.9) B9(-8.255,-1.9) B10(-6.985,-1.9) B11(-5.715,-1.9) B12(-4.445,-1.9) B13(-3.175,-1.9) B14(-1.905,-1.9) B15(-0.635,-1.9) B16(0.635,-1.9) B17(1.905,-1.9) B18(3.175,-1.9) B19(4.445,-1.9) B20(5.715,-1.9) B21(6.985,-1.9) B22(8.255,-1.9) B23(9.525,-1.9) B24(10.795,-1.9) B25(12.065,-1.9) B26(13.335,-1.9) B27(14.605,-1.9) B28(15.875,-1.9) B29(17.145,-1.9) B30(18.415,-1.9) C1(-18.415,-0.63) C2(-17.145,-0.63) C3(-15.875,-0.63) C4(-14.605,-0.63) C5(-13.335,-0.63) C6(-12.065,-0.63) C7(-10.795,-0.63) C8(-9.525,-0.63) C9(-8.255,-0.63) C10(-6.985,-0.63) C11(-5.715,-0.63) C12(-4.445,-0.63) C13(-3.175,-0.63) C14(-1.905,-0.63) C15(-0.635,-0.63) C16(0.635,-0.63) C17(1.905,-0.63) C18(3.175,-0.63) C19(4.445,-0.63) C20(5.715,-0.63) C21(6.985,-0.63) C22(8.255,-0.63) C23(9.525,-0.63) C24(10.795,-0.63) C25(12.065,-0.63) C26(13.335,-0.63) C27(14.605,-0.63) C28(15.875,-0.63) C29(17.145,-0.63) C30(18.415,-0.63) D1(-18.415,0.64) D2(-17.145,0.64) D3(-15.875,0.64) D4(-14.605,0.64) D5(-13.335,0.64) D6(-12.065,0.64) D7(-10.795,0.64) D8(-9.525,0.64) D9(-8.255,0.64) D10(-6.985,0.64) D11(-5.715,0.64) D12(-4.445,0.64) D13(-3.175,0.64) D14(-1.905,0.64) D15(-0.635,0.64) D16(0.635,0.64) D17(1.905,0.64) D18(3.175,0.64) D19(4.445,0.64) D20(5.715,0.64) D21(6.985,0.64) D22(8.255,0.64) D23(9.525,0.64) D24(10.795,0.64) D25(12.065,0.64) D26(13.335,0.64) D27(14.605,0.64) D28(15.875,0.64) D29(17.145,0.64) D30(18.415,0.64) E1(-18.415,1.91) E2(-17.145,1.91) E3(-15.875,1.91) E4(-14.605,1.91) E5(-13.335,1.91) E6(-12.065,1.91) E7(-10.795,1.91) E8(-9.525,1.91) E9(-8.255,1.91) E10(-6.985,1.91) E11(-5.715,1.91) E12(-4.445,1.91) E13(-3.175,1.91) E14(-1.905,1.91) E15(-0.635,1.91) E16(0.635,1.91) E17(1.905,1.91) E18(3.175,1.91) E19(4.445,1.91) E20(5.715,1.91) E21(6.985,1.91) E22(8.255,1.91) E23(9.525,1.91) E24(10.795,1.91) E25(12.065,1.91) E26(13.335,1.91) E27(14.605,1.91) E28(15.875,1.91) E29(17.145,1.91) E30(18.415,1.91)
DIO_SMC
  rect 2.21x3.099 smd: 1(-3.5,0) 2(3.5,0)
DIO_SOD523
  rect 0.559x0.432 smd: 1(-0.8,0) 2(0.8,0)
ETSSOP28_SN65HVS885_390X180_1-2
  rect 1.6x0.305 smd: 1(-2.8,4.225) 2(-2.8,3.575) 3(-2.8,2.925) 4(-2.8,2.275) 5(-2.8,1.625) 6(-2.8,0.975) 7(-2.8,0.325) 8(-2.8,-0.325) 9(-2.8,-0.975) 10(-2.8,-1.625) 11(-2.8,-2.275) 12(-2.8,-2.925) 13(-2.8,-3.575) 14(-2.8,-4.225) 15(2.8,-4.225) 16(2.8,-3.575) 17(2.8,-2.925) 18(2.8,-2.275) 19(2.8,-1.625) 20(2.8,-0.975) 21(2.8,-0.325) 22(2.8,0.325) 23(2.8,0.975) 24(2.8,1.625) 25(2.8,2.275) 26(2.8,2.925) 27(2.8,3.575) 28(2.8,4.225)
  rect 3.404x9.703 smd: 29(0,0)
FUSE_397_410X110_SMD_2-9
  rect 3.302x4.369 smd: 1(-5.045,0) 2(5.045,0)
HDR_2X3_TSW-103-07-D_S_T_8-4
  rect 1.702x1.702 hole 1.016: 1(0,0)
  round 1.702 hole 1.016: 2(0,2.54) 3(2.54,0) 4(2.54,2.54) 5(5.08,0) 6(5.08,2.54)
HDR_2X10_TSW_100_S_T
  rect 1.702x1.702 hole 1.016: 1(0,0)
  round 1.702 hole 1.016: 2(0,-2.54) 3(-2.54,0) 4(-2.54,-2.54) 5(-5.08,0) 6(-5.08,-2.54) 7(-7.62,0) 8(-7.62,-2.54) 9(-10.16,0) 10(-10.16,-2.54) 11(-12.7,0) 12(-12.7,-2.54) 13(-15.24,0) 14(-15.24,-2.54) 15(-17.78,0) 16(-17.78,-2.54) 17(-20.32,0) 18(-20.32,-2.54) 19(-22.86,0) 20(-22.86,-2.54)
HDR_3X1_100_S_T
  rect 1.803x1.803 hole 1.118: 1(0,0)
  round 1.803 hole 1.118: 2(-2.54,0) 3(-5.08,0)
HDR_5X2_100_S_T_8-6
  rect 1.702x1.702 hole 1.016: 1(0,0)
  round 1.702 hole 1.016: 2(0,-2.54) 3(-2.54,0) 4(-2.54,-2.54) 5(-5.08,0) 6(-5.08,-2.54) 7(-7.62,0) 8(-7.62,-2.54) 9(-10.16,0) 10(-10.16,-2.54)
HTSSOP28_LM5175-Q1_180X390_1-2
  rect 1.499x0.457 smd: 1(-2.9,4.225) 2(-2.9,3.575) 3(-2.9,2.925) 4(-2.9,2.275) 5(-2.9,1.625) 6(-2.9,0.975) 7(-2.9,0.325) 8(-2.9,-0.325) 9(-2.9,-0.975) 10(-2.9,-1.625) 11(-2.9,-2.275) 12(-2.9,-2.925) 13(-2.9,-3.575) 14(-2.9,-4.225) 15(2.9,-4.225) 16(2.9,-3.575) 17(2.9,-2.925) 18(2.9,-2.275) 19(2.9,-1.625) 20(2.9,-0.975) 21(2.9,-0.325) 22(2.9,0.325) 23(2.9,0.975) 24(2.9,1.625) 25(2.9,2.275) 26(2.9,2.925) 27(2.9,3.575) 28(2.9,4.225)
  rect 3.404x9.703 smd: 29(0,0)
LED_150060RS55040_70X40_SMD_0-5
  rect 0.787x0.762 smd: 1(-0.8,0) 2(0.8,0)
LED_150060SS75000_70X40_SMD_0-8
  rect 0.787x0.787 smd: 1(-0.8,0) 2(0.8,0)
QSOP24_25_340X150_1-8
  rect 1.499x0.406 smd: 1(-2.65,3.492) 2(-2.65,2.857) 3(-2.65,2.222) 4(-2.65,1.587) 5(-2.65,0.952) 6(-2.65,0.318) 7(-2.65,-0.317) 8(-2.65,-0.952) 9(-2.65,-1.587) 10(-2.65,-2.222) 11(-2.65,-2.857) 12(-2.65,-3.492) 13(2.65,-3.492) 14(2.65,-2.857) 15(2.65,-2.222) 16(2.65,-1.587) 17(2.65,-0.952) 18(2.65,-0.317) 19(2.65,0.318) 20(2.65,0.952) 21(2.65,1.587) 22(2.65,2.222) 23(2.65,2.857) 24(2.65,3.492)
RECPT_2X3_PPTC032LFBN_S_T_8-5
  rect 1.702x1.702 hole 1.016: 1(0,0)
  round 1.702 hole 1.016: 2(0,-2.54) 3(2.54,0) 4(2.54,-2.54) 5(5.08,0) 6(5.08,-2.54)
RECPT_2X10_68683-310_S_T_7-1
  rect 1.448x1.448 hole 0.762: 1(0,0)
  round 1.448 hole 0.762: 2(0,-2.54) 3(2.54,0) 4(2.54,-2.54) 5(5.08,0) 6(5.08,-2.54) 7(7.62,0) 8(7.62,-2.54) 9(10.16,0) 10(10.16,-2.54) 11(12.7,0) 12(12.7,-2.54) 13(15.24,0) 14(15.24,-2.54) 15(17.78,0) 16(17.78,-2.54) 17(20.32,0) 18(20.32,-2.54) 19(22.86,0) 20(22.86,-2.54)
RES0402_0-5
  rect 0.559x0.635 smd: 1(-0.49,0) 2(0.49,0)
RES0402_1
  rect 0.559x0.635 smd: 1(-0.49,0) 2(0.49,0)
RES0603_0-5
  rect 0.635x0.991 smd: 1(-0.74,0) 2(0.74,0)
RES0805_0-75
  rect 1.194x1.448 smd: 1(-0.95,0) 2(0.95,0)
RES_MELF0102_1-1
  rect 0.787x1.295 smd: 1(-0.95,0) 2(0.95,0)
SOIC8_1-8
  rect 1.549x0.61 smd: 1(-2.7,1.905) 2(-2.7,0.635) 3(-2.7,-0.635) 4(-2.7,-1.905) 5(2.7,-1.905) 6(2.7,-0.635) 7(2.7,0.635) 8(2.7,1.905)
SOT23-5
  rect 1.092x0.61 smd: 1(-1.3,0.95) 2(-1.3,0) 3(-1.3,-0.95) 4(1.3,-0.95) 5(1.3,0.95)
SOT23-123_1-1
  rect 1.016x0.61 smd: 1(-1.15,0.95) 2(-1.15,-0.95) 3(1.15,0)
SOT23-123_1-2
  rect 1.016x0.61 smd: 1(-1.15,0.95) 2(-1.15,-0.95) 3(1.15,0)
TP20_SMD
  round 0.508 smd: 1(0,0)
TSSOP20_25-59_260X180_1-2
  rect 1.499x0.457 smd: 1(-2.9,2.925) 2(-2.9,2.275) 3(-2.9,1.625) 4(-2.9,0.975) 5(-2.9,0.325) 6(-2.9,-0.325) 7(-2.9,-0.975) 8(-2.9,-1.625) 9(-2.9,-2.275) 10(-2.9,-2.925) 11(2.9,-2.925) 12(2.9,-2.275) 13(2.9,-1.625) 14(2.9,-0.975) 15(2.9,-0.325) 16(2.9,0.325) 17(2.9,0.975) 18(2.9,1.625) 19(2.9,2.275) 20(2.9,2.925)
TSSOP48_19-68_500X245_1-2
  rect 1.499x0.305 smd: 1(-3.75,5.75) 2(-3.75,5.25) 3(-3.75,4.75) 4(-3.75,4.25) 5(-3.75,3.75) 6(-3.75,3.25) 7(-3.75,2.75) 8(-3.75,2.25) 9(-3.75,1.75) 10(-3.75,1.25) 11(-3.75,0.75) 12(-3.75,0.25) 13(-3.75,-0.25) 14(-3.75,-0.75) 15(-3.75,-1.25) 16(-3.75,-1.75) 17(-3.75,-2.25) 18(-3.75,-2.75) 19(-3.75,-3.25) 20(-3.75,-3.75) 21(-3.75,-4.25) 22(-3.75,-4.75) 23(-3.75,-5.25) 24(-3.75,-5.75) 25(3.75,-5.75) 26(3.75,-5.25) 27(3.75,-4.75) 28(3.75,-4.25) 29(3.75,-3.75) 30(3.75,-3.25) 31(3.75,-2.75) 32(3.75,-2.25) 33(3.75,-1.75) 34(3.75,-1.25) 35(3.75,-0.75) 36(3.75,-0.25) 37(3.75,0.25) 38(3.75,0.75) 39(3.75,1.25) 40(3.75,1.75) 41(3.75,2.25) 42(3.75,2.75) 43(3.75,3.25) 44(3.75,3.75) 45(3.75,4.25) 46(3.75,4.75) 47(3.75,5.25) 48(3.75,5.75)
unnamed#2
  round 2.616 hole 2.743 unplated: (0,0)
unnamed#3
  round 1.651 hole 1.016: 1(0,0)
unnamed#4
  round 0.686 hole 0.813 unplated: (-1.27,1.254) (0,1.254) (1.27,1.254)
VSON10_19-68_120X100_1
  rect 0.787x0.305 smd: 1(-1.5,1) 2(-1.5,0.5) 3(-1.5,0) 4(-1.5,-0.5) 5(-1.5,-1) 6(1.5,-1) 7(1.5,-0.5) 8(1.5,0) 9(1.5,0.5) 10(1.5,1)
  rect 1.753x2.057 smd: 11(0,0)

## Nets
5VOP: C92.1 C93.1 C94.1 U37.15(5VOP) U38.5(VCC)
